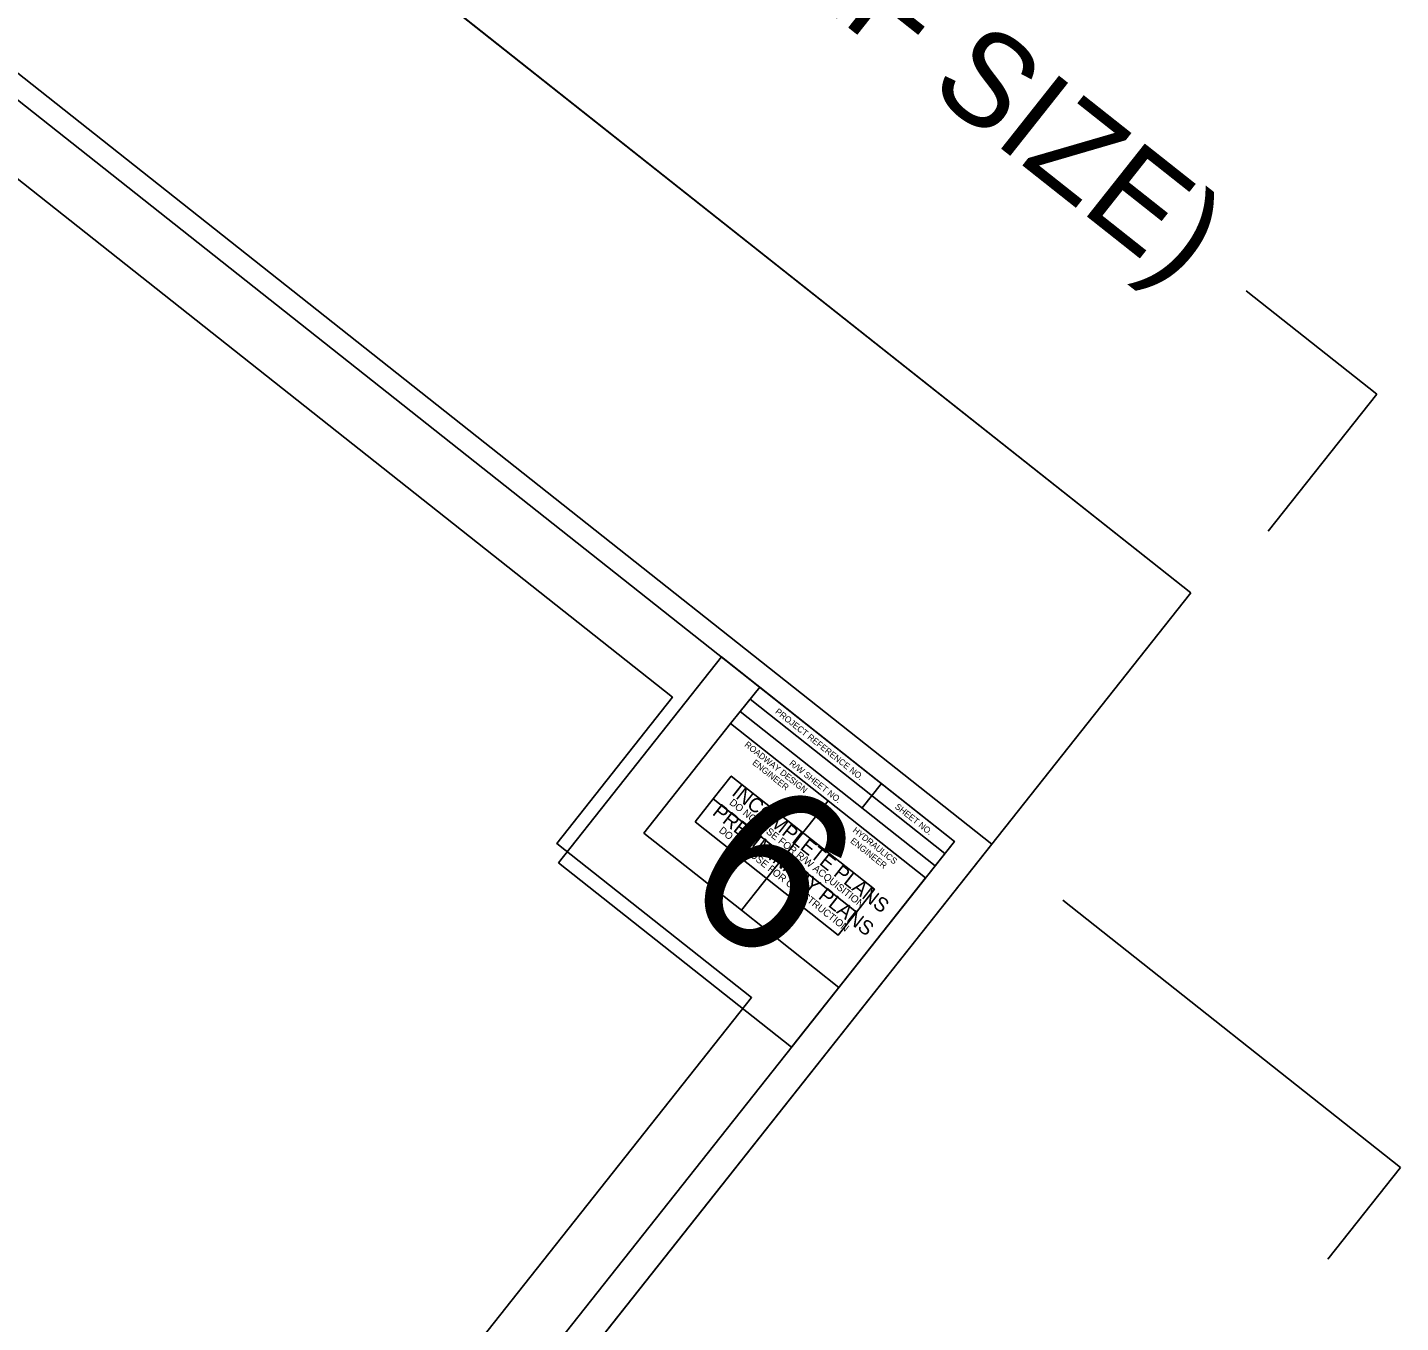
# Model space of a CAD drawing. Extents: x 1778994 to 1784559, y 810461 to 816654.
# Drawn here: x 1783454 to 1784559, y 812174 to 813217 of the extents above; entities that cross this region are included whole.
import ezdxf

# ---------------------------------------------------------------- set-up
doc = ezdxf.new("R2010")
doc.units = 0
for name, color, linetype in [('Sheet Clip Boundary CELL', 7, 'Continuous'), ('Sheet Cutting Line CELL', 7, 'Continuous'), ('Sheet Detail CELL', 7, 'Continuous'), ('Sheet Plan Layout CELL', 7, 'Continuous'), ('Sheet Plot Border Inside CELL', 7, 'Continuous'), ('Sheet Plot Border Outside CELL', 7, 'Continuous'), ('Sheet Sticker Incomplete CELL', 7, 'Continuous'), ('Sheet Sticker Preliminary CELL', 7, 'Continuous')]:
    doc.layers.add(name, color=color, linetype=linetype)

msp = doc.modelspace()

# ---------------------------------------------------------------- linework, layer by layer
at = {"layer": 'Sheet Clip Boundary CELL'}
msp.add_lwpolyline([(1780971.5, 813236.4), (1781770.7, 814245.9), (1782005.9, 814059.6), (1782091.3, 814167.4), (1783972.9, 812677.7), (1783879.8, 812560.1), (1784036.6, 812435.9), (1783245.2, 811436.3)], close=True, dxfattribs=at)
at = {"layer": 'Sheet Cutting Line CELL'}
msp.add_line((1784390.3, 812761.8), (1781749.7, 814852.4), dxfattribs=at)
at = {"layer": 'Sheet Detail CELL'}
for p, q in [((1784539.9, 812921.9), (1784434.8, 813005.1)), ((1784452.4, 812811.4), (1784539.9, 812921.9)), ((1784035.4, 812676.1), (1784192.2, 812551.9)), ((1784027.6, 812666.3), (1784019.8, 812656.5)), ((1784027.6, 812666.3), (1784184.4, 812542.1)), ((1784027.6, 812666.3), (1784184.4, 812542.1)), ((1784141.2, 812608.2), (1784125.6, 812588.6)), ((1784098.3, 812594.4), (1784028.5, 812506.2)), ((1784287.2, 812514.3), (1784559.1, 812299.1)), ((1784559.1, 812299.1), (1784500.6, 812225.3))]:
    msp.add_line(p, q, dxfattribs=at)
for points in [[(1781847.9, 814423.9), (1784200, 812561.7), (1783175.8, 811268.1), (1780823.7, 813130.3)], [(1784043.2, 812685.9), (1784200, 812561.7), (1784184.4, 812542.1), (1784027.6, 812666.3)], [(1784019.8, 812656.5), (1784098.3, 812594.4), (1784028.5, 812506.2), (1783950, 812568.3)], [(1784098.3, 812594.4), (1784176.7, 812532.3), (1784106.9, 812444.1), (1784028.5, 812506.2)]]:
    msp.add_lwpolyline(points, close=True, dxfattribs=at)
at = {"layer": 'Sheet Plan Layout CELL'}
msp.add_lwpolyline([(1783881.1, 812544.5), (1784068.7, 812395.9), (1784200, 812561.7), (1784012.4, 812710.3)], close=True, dxfattribs=at)
at = {"layer": 'Sheet Plot Border Inside CELL'}
msp.add_lwpolyline([(1784230.1, 812559.5), (1781642.9, 814607.9), (1780597.6, 813287.6), (1783184.8, 811239.2)], close=True, dxfattribs=at)
at = {"layer": 'Sheet Plot Border Outside CELL'}
msp.add_lwpolyline([(1784390.3, 812761.8), (1781749.7, 814852.4), (1780384.1, 813127.6), (1783024.7, 811037)], close=True, dxfattribs=at)
at = {"layer": 'Sheet Sticker Incomplete CELL'}
msp.add_lwpolyline([(1784005.7, 812595.9), (1784020.3, 812614.3), (1784135.6, 812523.1), (1784121, 812504.6)], close=True, dxfattribs=at)
at = {"layer": 'Sheet Sticker Preliminary CELL'}
msp.add_lwpolyline([(1783991.2, 812577.5), (1784005.7, 812595.9), (1784121, 812504.6), (1784106.4, 812486.2)], close=True, dxfattribs=at)

# ---------------------------------------------------------------- texts
at = {"layer": 'Sheet Detail CELL'}
for s, height, p in [('TO PLOT 34"(HALF SIZE)', 75, (1783455.2, 813738.9)), ('PROJECT REFERENCE NO.', 5, (1784055.2, 812665.3)), ('ROADWAY DESIGN', 5, (1784030.5, 812638.7)), ('ENGINEER', 5, (1784036.8, 812624.1)), ('R/W SHEET NO.', 5, (1784066.6, 812623.7)), ('SHEET NO.', 5, (1784151.6, 812588.8)), ('HYDRAULICS', 5, (1784117.6, 812569.7)), ('ENGINEER', 5, (1784115.7, 812561.1))]:
    msp.add_text(s, height=height, rotation=321.6309, dxfattribs=at).set_placement(p)
at = {"layer": 'Sheet Plan Layout CELL'}
msp.add_text('6', height=131.3, rotation=321.6755, dxfattribs=at).set_placement((1783974.6, 812518.3))
at = {"layer": 'Sheet Sticker Incomplete CELL'}
for s, height, p in [('INCOMPLETE PLANS', 11.52, (1784020, 812599.5)), ('DO NOT USE FOR R/W ACQUISITION', 5.76, (1784018.3, 812592))]:
    msp.add_text(s, height=height, rotation=321.6309, dxfattribs=at).set_placement(p)
at = {"layer": 'Sheet Sticker Preliminary CELL'}
for s, height, p in [('PRELIMINARY PLANS', 11.52, (1784004.4, 812583.7)), ('DO NOT USE FOR CONSTRUCTION', 5.76, (1784009.9, 812569.6))]:
    msp.add_text(s, height=height, rotation=321.6309, dxfattribs=at).set_placement(p)

doc.saveas('drawing.dxf')
